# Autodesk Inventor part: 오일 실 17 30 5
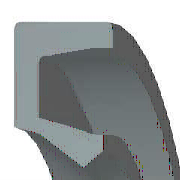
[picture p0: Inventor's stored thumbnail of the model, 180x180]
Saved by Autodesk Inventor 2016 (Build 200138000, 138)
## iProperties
IsCustomPart: 1
Created: 2012-02
Part Number: 오일 실 17 30 5
Material: 고무
Description: 오일 실 - 비스프링, 금속 케이스 GM
Document SubType Name: Modeling
Standard: JIS B 2402
Designer: mduedu
Standards Organization: JIS
Language: ko-KR
Size Designation: 17 30 5 B
Categories: <MemberInstance><Categories><Category DisplayName="샤프트 부품" InternalName="7f7aeb1f-a693-4053-b835-cee3144e0d98" Mnemonic="SHFT"><Category DisplayName="실링" Intern
Density: 0.93 g/cm^3
Appearance: Rubber-Black
Author: mduedu
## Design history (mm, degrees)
body "Solid1"
revolve "회전1" stored, may be unused: angle "d27" = 360 deg
fillet "모깎기1" dims "d28" = 0.25 (= 0.05 x b)
chamfer "모따기1" distance "d29" = 0.07143 (= 0.0142857 x b); stored, may be unused: second distance "d30" = 0.25 (= 0.05 x b), angle "d35" = 45 deg
sketch "스케치2"
  geometry: L1 (-9.367, -3.238)-(-10.233, -3.863); L2 (-8.5, -1.625)-(-9.367, -3.238); L3 (-9.15, -1)-(-8.5, -1.625); L4 (-11.317, -3.75)-(-9.15, -1); L5 (-13.075, -3.75)-(-11.317, -3.75); L6 (-14.375, -1.25)-(-13.075, -3.75); L7 (-14.375, 0)-(-14.375, -1.25); L8 (-15, 0)-(-14.375, 0); L9 (-15, -5)-(-15, 0); L10 (-11.129, -5)-(-15, -5); L11 (-10.233, -3.863)-(-11.129, -5); L12 (0, -9.6)-(0, 1.6) reference; L13 (-14, 0)-(-28, 0) reference
  constraints: 22 end point, 3 horizontal, 2 vertical, 1 parallel
  dimensions: "d2" = 5 distance of L9.start L8.start (= b); "d4" = 1 vertical distance of L8.start L3.start (= 0.2 x b); "d6" = 0.625 distance of L8.start L7.start (= 0.125 x b); "d8" = 1.25 distance of L7.start L6.start (= 0.25 x b); "d10" = 1.25 vertical distance of L5.start L9.start (= 0.25 x b); "d12" = 1.3 horizontal distance of L6.start L5.start (= 0.1 x dd - 0.1 x Diam); "d14" = 1.6129 vertical distance of L2.start L1.start (= 0.322581 x b); "d16" = 0.86667 horizontal distance of L1.start L1.end (= 0.0666667 x dd - 0.0666667 x Diam); "d18" = 0.86667 horizontal distance of L2.start L1.start (= 0.0666667 x dd - 0.0666667 x Diam); "d20" = 0.625 vertical distance of L3.start L2.start (= 0.125 x b); "d22" = 0.65 horizontal distance of L3.start L2.start (= 0.05 x dd - 0.05 x Diam); "d24" = 0.625 vertical distance of L1.start L1.end (= 0.125 x b); "d26" = 2.16667 horizontal distance of L4.start L3.start (= 0.166667 x dd - 0.166667 x Diam); "d31" = 0 distance between parallel lines of L8 L13; "d32" = 15 distance between parallel lines of L12 L9 (= 0.5 x dd); "d33" = 8.5 distance from line of L12 L2.start (= 0.5 x Diam)
other parameters: "Diam" = 17 [user parameter; used in 6 equation terms], "b" = 5 [user parameter; used in 11 equation terms], "d1" = 8 (derived), "d3" = 1.6 (derived), "d5" = 1 (derived), "d7" = 2 (derived), "d9" = 2 (derived), "d11" = 2 (derived), "d13" = 2.58065 (derived), "d15" = 1.33333 (derived), "d17" = 1.33333 (derived), "d19" = 1 (derived), "d21" = 1 (derived), "d23" = 1 (derived), "d25" = 3.33333 (derived), "d34" = 0
